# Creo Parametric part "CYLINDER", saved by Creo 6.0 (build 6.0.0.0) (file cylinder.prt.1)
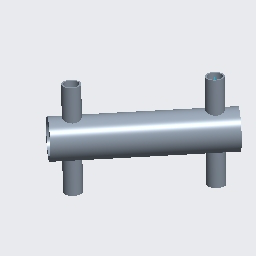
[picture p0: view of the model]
Units: millimeter Newton Second (mmNs); MM, TONNE, SECS

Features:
  1. datum plane "RIGHT"
  2. datum plane "TOP"
  3. datum plane "FRONT"
  4. coordinate system
  5. curve
  6. protrusion
  7. sketch "Sketch 2"
  8. protrusion "Sweep 4"
  9. sketch "Sketch 6"
  10. extruded cut "Extrude 5"
  11. datum plane "DTM1"
  12. mirror "Mirror 1"
  13. protrusion "Sweep 4 (2)"
  14. sketch "Sketch 6 (2)"
  15. extruded cut "Extrude 5 (2)"
  16. mirror "Mirror 2"
  17. protrusion "Sweep 4 (3)"
  18. sketch "Sketch 6 (3)"
  19. extruded cut "Extrude 5 (3)"
  20. protrusion "Sweep 4 (4)"
  21. sketch "Sketch 6 (4)"
  22. extruded cut "Extrude 5 (4)"

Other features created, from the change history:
  sketch "Sketch 3" (4 times)
  datum plane "DTM1" (2 times)
  extrusion "Extrude 2"
  sketch "Sketch 4" (2 times)
  protrusion "Sweep 1" (3 times)
  extruded cut "Extrude 2" (2 times)
  datum plane "DTM2" (2 times)
  datum plane "DTM3" (3 times)
  mirror "Mirror 1" (4 times)
  protrusion "Sweep 1 (2)" (2 times)
  sketch "Sketch 4 (2)"
  extruded cut "Extrude 2 (2)" (3 times)
  mirror "Mirror 2" (2 times)
  protrusion "Sweep 1 (3)" (2 times)
  sketch "Sketch 4 (3)"
  extruded cut "Extrude 2 (3)" (2 times)
  protrusion "Sweep 1 (4)" (2 times)
  sketch "Sketch 4 (4)"
  extruded cut "Extrude 2 (4)" (2 times)
  sketch "Sketch 3 (2)" (2 times)
  sketch "Sketch 3 (3)"
  sketch "Sketch 3 (4)"
  datum plane "DTM4"
  sketch "Sketch 6 (2)"
  extruded cut "Extrude 5 (2)"

Surfaces: 18 cylinder, 6 plane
